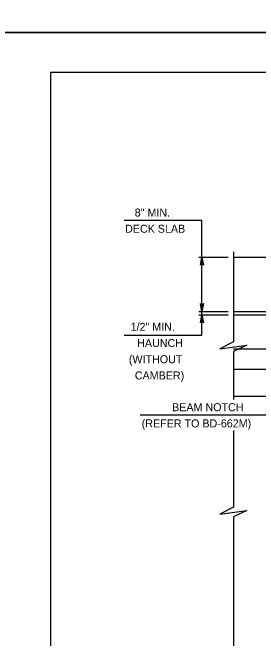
# Model space of a CAD drawing. Extents: x 636530 to 644067, y 294168 to 299122.
# Drawn here: x 639032.6 to 639124.7, y 295723.5 to 295958 of the extents above; entities that cross this region are included whole.
import ezdxf

# ---------------------------------------------------------------- set-up
doc = ezdxf.new("R2010")
doc.units = 0
doc.layers.add('1', color=7, linetype='Continuous')
doc.layers.add('PLT-BNDY', color=7, linetype='Continuous')

msp = doc.modelspace()

# ---------------------------------------------------------------- linework, layer by layer
at = {"layer": '1'}
for p, q in [((639832.78, 295935.48), (639046.78, 295935.48)), ((639046.78, 295935.48), (639046.78, 295371.48)), ((639074.37, 295880.15), (639103.54, 295880.15)), ((639103.54, 295845.98), (639103.54, 295880.15)), ((639115.37, 295868.28), (639115.37, 295834.55)), ((639102.43, 295866.3), (639113.42, 295866.3)), ((639115.37, 295866.3), (639217.06, 295866.3)), ((639102.43, 295845.98), (639113.42, 295845.98)), ((639102.43, 295844.71), (639113.42, 295844.71)), ((639103.54, 295837.15), (639103.54, 295845.98)), ((639115.37, 295845.98), (639152.19, 295845.98)), ((639115.37, 295844.71), (639153.46, 295844.71)), ((639074.37, 295837.15), (639103.54, 295837.15)), ((639115.37, 295832.01), (639166.16, 295832.01)), ((639115.37, 295831.03), (639115.37, 295812.96)), ((639115.37, 295824.39), (639173.78, 295824.39)), ((639115.37, 295814.23), (639177.59, 295814.23)), ((639080.4, 295807.3), (639132.07, 295807.3)), ((639115.37, 295801.38), (639115.37, 295772.6)), ((639115.37, 295769.09), (639115.37, 295716.66))]:
    msp.add_line(p, q, dxfattribs=at)
for points in [[(639103.54, 295866.3), (639104.1, 295863.31), (639104.02, 295863.43), (639103.94, 295863.54), (639103.84, 295863.6), (639103.74, 295863.66), (639103.64, 295863.68), (639103.54, 295863.7), (639103.44, 295863.68), (639103.34, 295863.66), (639103.24, 295863.6), (639103.14, 295863.54), (639103.06, 295863.43), (639102.98, 295863.31), (639103.54, 295866.3), (639103.06, 295863.43), (639103.14, 295863.54), (639103.54, 295866.3), (639103.24, 295863.6), (639103.34, 295863.66), (639103.54, 295866.3), (639103.44, 295863.68), (639103.54, 295863.7), (639103.54, 295866.3), (639103.64, 295863.68), (639103.74, 295863.66), (639103.54, 295866.3), (639103.84, 295863.6), (639103.94, 295863.54), (639103.54, 295866.3), (639104.02, 295863.43)], [(639103.54, 295845.98), (639102.98, 295848.96), (639103.06, 295848.84), (639103.14, 295848.73), (639103.24, 295848.67), (639103.34, 295848.61), (639103.44, 295848.59), (639103.54, 295848.58), (639103.64, 295848.59), (639103.74, 295848.61), (639103.84, 295848.67), (639103.94, 295848.73), (639104.02, 295848.84), (639104.1, 295848.96), (639103.54, 295845.98), (639104.02, 295848.84), (639103.94, 295848.73), (639103.54, 295845.98), (639103.84, 295848.67), (639103.74, 295848.61), (639103.54, 295845.98), (639103.64, 295848.59), (639103.54, 295848.58), (639103.54, 295845.98), (639103.44, 295848.59), (639103.34, 295848.61), (639103.54, 295845.98), (639103.24, 295848.67), (639103.14, 295848.73), (639103.54, 295845.98), (639103.06, 295848.84)], [(639103.54, 295844.71), (639104.1, 295841.73), (639104.02, 295841.84), (639103.94, 295841.96), (639103.84, 295842.01), (639103.74, 295842.07), (639103.64, 295842.09), (639103.54, 295842.11), (639103.44, 295842.09), (639103.34, 295842.07), (639103.24, 295842.01), (639103.14, 295841.96), (639103.06, 295841.84), (639102.98, 295841.73), (639103.54, 295844.71), (639103.06, 295841.84), (639103.14, 295841.96), (639103.54, 295844.71), (639103.24, 295842.01), (639103.34, 295842.07), (639103.54, 295844.71), (639103.44, 295842.09), (639103.54, 295842.11), (639103.54, 295844.71), (639103.64, 295842.09), (639103.74, 295842.07), (639103.54, 295844.71), (639103.84, 295842.01), (639103.94, 295841.96), (639103.54, 295844.71), (639104.02, 295841.84)], [(639115.37, 295834.55), (639110.18, 295832.01), (639120.33, 295833.39), (639115.37, 295831.03)], [(639115.37, 295772.6), (639110.18, 295770.07), (639120.33, 295771.45), (639115.37, 295769.09)]]:
    msp.add_lwpolyline(points, dxfattribs=at)
at = {"layer": 'PLT-BNDY'}
for points in [[(639006.78, 296544.48), (639847.78, 296544.48), (639847.78, 295950.48), (639006.78, 295950.48)], [(639006.78, 295950.48), (639847.78, 295950.48), (639847.78, 295356.48), (639006.78, 295356.48)]]:
    msp.add_lwpolyline(points, close=True, dxfattribs=at)

# ---------------------------------------------------------------- texts
at = {"layer": '1'}
for s, p in [('8" MIN.', (639078.36, 295881.54)), ('DECK SLAB', (639074.75, 295875.47)), ('1/2" MIN.', (639076.82, 295838.72)), ('HAUNCH', (639079.28, 295832.65)), ('(WITHOUT', (639076.16, 295826.58)), ('CAMBER)', (639078.41, 295820.51)), ('BEAM NOTCH', (639092.37, 295808.61)), ('(REFER TO BD-662M)', (639080.98, 295802.54))]:
    msp.add_text(s, height=3, rotation=360, dxfattribs=at).set_placement(p)

doc.saveas('drawing.dxf')
